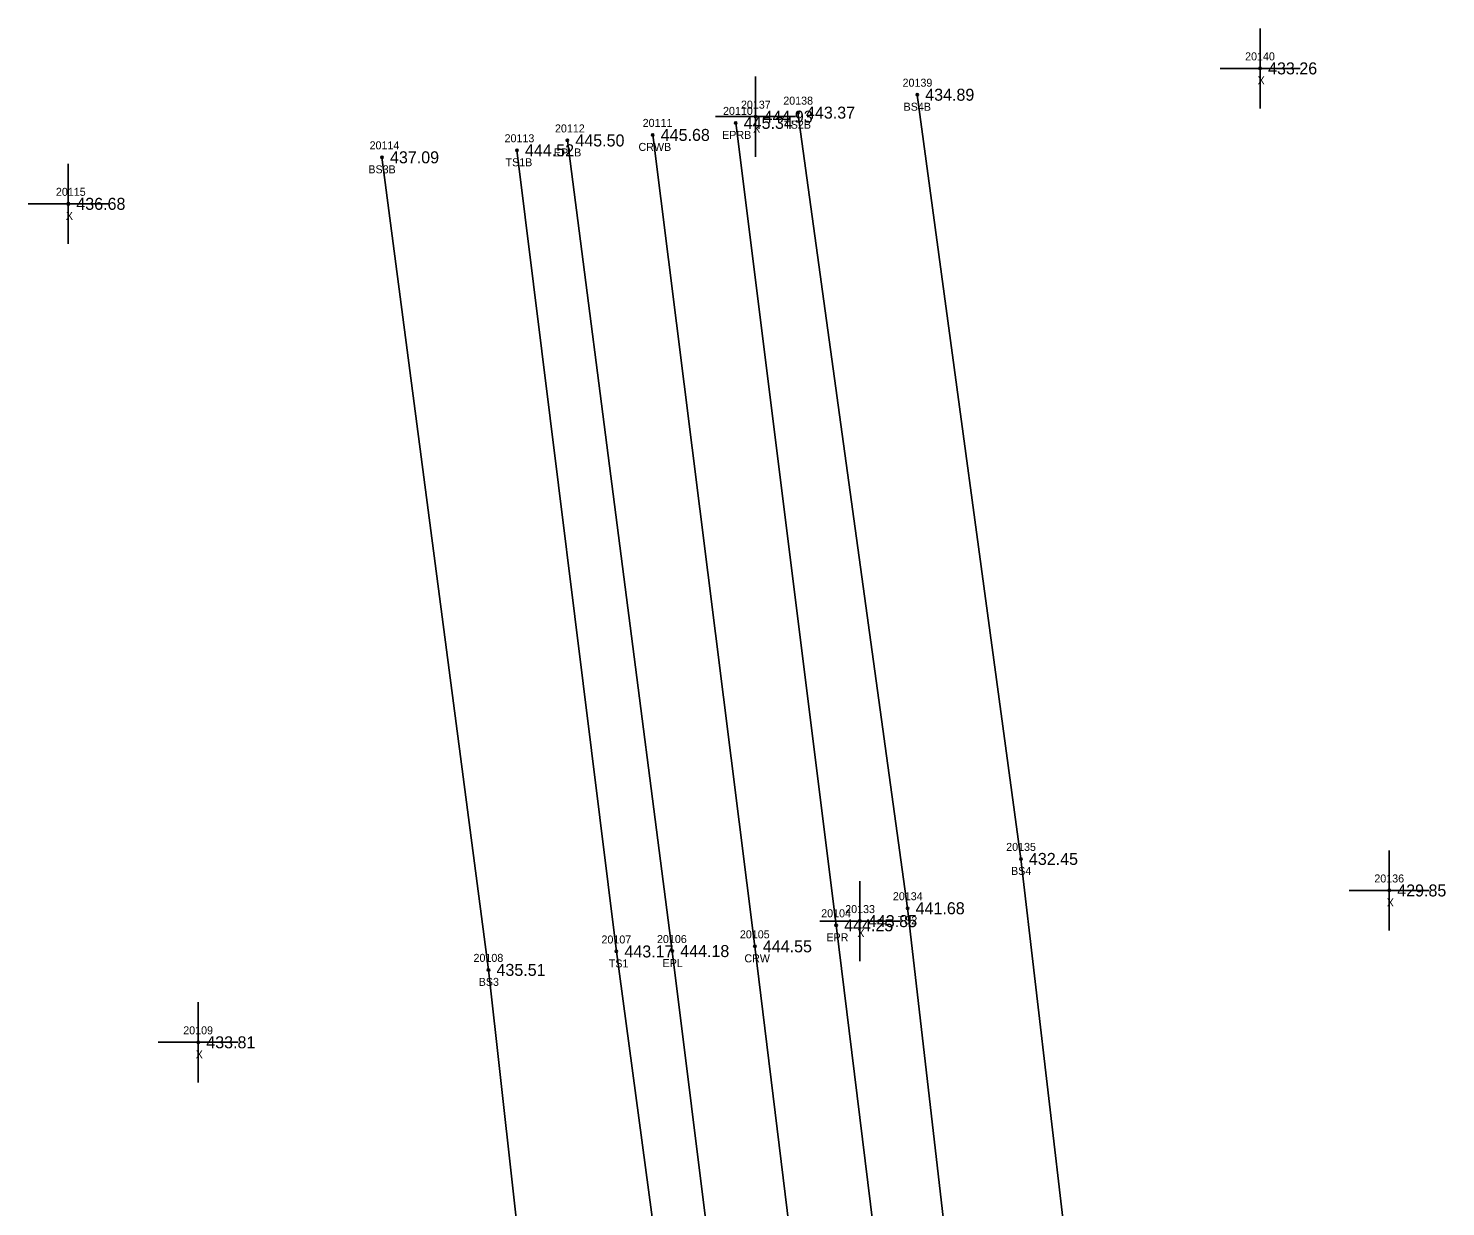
# Model space of a CAD drawing. Extents: x 1858461 to 1858936, y 1147060 to 1148183.
# Drawn here: x 1858539.2 to 1858716.4, y 1148023.6 to 1148170.7 of the extents above; entities that cross this region are included whole.
import ezdxf

# ---------------------------------------------------------------- set-up
doc = ezdxf.new("R2010")
doc.units = 0
for name, color, linetype in [('RD_DTM_BkLn1', 7, 'Continuous'), ('RD_DTM_BkLn2', 7, 'Continuous'), ('RD_DTM_BkLn_txCode', 7, 'Continuous'), ('RD_EX_Misc', 7, 'Continuous'), ('RD_EX_Misc_txCode', 7, 'Continuous'), ('RD_EX_Road', 7, 'Continuous'), ('RD_EX_Road_txCode', 7, 'Continuous'), ('RD_EX_TX_Misc_ELEV', 7, 'Continuous'), ('RD_EX_TX_Road_ELEV', 7, 'Continuous'), ('RD_HC_Survey_ELEV', 7, 'Continuous'), ('RD_HC_Survey_txCode', 7, 'Continuous'), ('RD_SMD_Locator', 7, 'Continuous')]:
    doc.layers.add(name, color=color, linetype=linetype)

msp = doc.modelspace()

# ---------------------------------------------------------------- linework, layer by layer
at = {"layer": 'RD_DTM_BkLn1'}
msp.add_lwpolyline([(1858679.02, 1147660.19), (1858666.85, 1147759.91), (1858654.47, 1147859.47), (1858641.87, 1147959.15), (1858630.02, 1148056.08), (1858617.26, 1148157.44)], dxfattribs=at)
at = {"layer": 'RD_DTM_BkLn2'}
for points in [[(1858693.62, 1147653.8), (1858703.51, 1147658.34), (1858709.65, 1147670.29), (1858700.15, 1147768.19), (1858693.67, 1147865.34), (1858675.79, 1147959.77), (1858663.27, 1148067), (1858650.31, 1148162.46)], [(1858691.24, 1147663), (1858693.74, 1147672.32), (1858681.4, 1147761.99), (1858668.07, 1147861.46), (1858660.68, 1147960.55), (1858649.11, 1148060.84), (1858635.41, 1148160.22)], [(1858693.62, 1147653.8), (1858663.6, 1147639.15), (1858647.78, 1147639.17), (1858628.12, 1147754.45), (1858616.79, 1147851.29), (1858607.32, 1147958.26), (1858596.73, 1148053.14), (1858583.42, 1148154.64)], [(1858665.51, 1147658.67), (1858661.09, 1147664.96), (1858652.2, 1147758.21), (1858640.05, 1147857.23), (1858625.95, 1147957.13), (1858612.72, 1148055.44), (1858600.29, 1148155.52)]]:
    msp.add_lwpolyline(points, dxfattribs=at)
at = {"layer": 'RD_EX_Misc'}
for p, q in [((1858693.16, 1148160.75), (1858693.16, 1148170.75)), ((1858630.11, 1148154.72), (1858630.11, 1148164.72)), ((1858688.16, 1148165.75), (1858698.16, 1148165.75)), ((1858625.11, 1148159.72), (1858635.11, 1148159.72)), ((1858544.22, 1148143.83), (1858544.22, 1148153.83)), ((1858539.22, 1148148.83), (1858549.22, 1148148.83)), ((1858709.3, 1148058.06), (1858709.3, 1148068.06)), ((1858643.15, 1148054.23), (1858643.15, 1148064.23)), ((1858704.3, 1148063.06), (1858714.3, 1148063.06)), ((1858638.15, 1148059.23), (1858648.15, 1148059.23)), ((1858560.46, 1148039.09), (1858560.46, 1148049.09)), ((1858555.46, 1148044.09), (1858565.46, 1148044.09))]:
    msp.add_line(p, q, dxfattribs=at)
at = {"layer": 'RD_EX_Road'}
for points in [[(1858679.02, 1147660.19), (1858688.73, 1147661.54), (1858677.21, 1147761.6), (1858664.75, 1147860.38), (1858652.33, 1147959.9), (1858640.18, 1148058.71), (1858627.63, 1148158.94)], [(1858679.02, 1147660.19), (1858669.49, 1147658.82), (1858657, 1147758.92), (1858643.96, 1147857.84), (1858631.87, 1147958), (1858619.69, 1148055.49), (1858606.59, 1148156.75)]]:
    msp.add_lwpolyline(points, dxfattribs=at)
at = {"layer": 'RD_SMD_Locator'}
for centre in [(1858693.16, 1148165.75), (1858650.31, 1148162.46), (1858630.11, 1148159.72), (1858635.41, 1148160.22), (1858617.26, 1148157.44), (1858627.63, 1148158.94), (1858600.29, 1148155.52), (1858606.59, 1148156.75), (1858583.42, 1148154.64), (1858544.22, 1148148.83), (1858663.27, 1148067), (1858709.3, 1148063.06), (1858649.11, 1148060.84), (1858640.18, 1148058.71), (1858643.15, 1148059.23), (1858612.72, 1148055.44), (1858619.69, 1148055.49), (1858630.02, 1148056.08), (1858596.73, 1148053.14), (1858560.46, 1148044.09)]:
    msp.add_circle(centre, 0.15, dxfattribs=at)

# ---------------------------------------------------------------- texts
at = {"layer": 'RD_DTM_BkLn_txCode'}
for s, p in [('20139', (1858648.48, 1148163.46)), ('20138', (1858633.57, 1148161.22)), ('BS4B', (1858648.61, 1148160.46)), ('TS2B', (1858633.69, 1148158.22)), ('20113', (1858598.74, 1148156.52)), ('20114', (1858581.87, 1148155.64)), ('TS1B', (1858598.86, 1148153.52)), ('BS3B', (1858581.72, 1148152.64)), ('20135', (1858661.43, 1148068)), ('BS4', (1858662.04, 1148065)), ('20134', (1858647.27, 1148061.84)), ('TS2', (1858647.86, 1148058.84)), ('20107', (1858610.85, 1148056.44)), ('20108', (1858594.86, 1148054.14)), ('TS1', (1858611.76, 1148053.44)), ('BS3', (1858595.51, 1148051.14))]:
    msp.add_text(s, height=1, dxfattribs=at).set_placement(p)
at = {"layer": 'RD_EX_Misc_txCode'}
for s, p in [('20140', (1858691.29, 1148166.75)), ('X', (1858692.85, 1148163.75)), ('20137', (1858628.28, 1148160.72)), ('X', (1858629.8, 1148157.72)), ('20115', (1858542.67, 1148149.83)), ('X', (1858543.91, 1148146.83)), ('20136', (1858707.44, 1148064.06)), ('X', (1858708.99, 1148061.06)), ('20133', (1858641.31, 1148060.23)), ('X', (1858642.83, 1148057.23)), ('20109', (1858558.58, 1148045.09)), ('X', (1858560.14, 1148042.09))]:
    msp.add_text(s, height=1, dxfattribs=at).set_placement(p)
at = {"layer": 'RD_EX_Road_txCode'}
for s, p in [('20110', (1858626.04, 1148159.94)), ('20112', (1858605.04, 1148157.75)), ('EPRB', (1858625.93, 1148156.94)), ('EPLB', (1858604.91, 1148154.75)), ('20104', (1858638.31, 1148059.71)), ('20106', (1858617.79, 1148056.49)), ('EPR', (1858638.96, 1148056.71)), ('EPL', (1858618.49, 1148053.49))]:
    msp.add_text(s, height=1, dxfattribs=at).set_placement(p)
at = {"layer": 'RD_EX_TX_Misc_ELEV'}
for s, p in [('433.26', (1858694.16, 1148165)), ('434.89', (1858651.31, 1148161.71)), ('443.37', (1858636.41, 1148159.47)), ('444.93', (1858631.11, 1148158.97)), ('444.52', (1858601.29, 1148154.77)), ('437.09', (1858584.42, 1148153.89)), ('436.68', (1858545.22, 1148148.08)), ('432.45', (1858664.27, 1148066.25)), ('429.85', (1858710.3, 1148062.31)), ('443.85', (1858644.15, 1148058.48)), ('441.68', (1858650.11, 1148060.09)), ('443.17', (1858613.72, 1148054.69)), ('435.51', (1858597.73, 1148052.39)), ('433.81', (1858561.46, 1148043.34))]:
    msp.add_text(s, height=1.5, dxfattribs=at).set_placement(p)
at = {"layer": 'RD_EX_TX_Road_ELEV'}
for s, p in [('445.34', (1858628.63, 1148158.19)), ('445.50', (1858607.59, 1148156)), ('444.25', (1858641.18, 1148057.96)), ('444.18', (1858620.69, 1148054.74))]:
    msp.add_text(s, height=1.5, dxfattribs=at).set_placement(p)
at = {"layer": 'RD_HC_Survey_ELEV'}
for s, p in [('445.68', (1858618.26, 1148156.69)), ('444.55', (1858631.02, 1148055.33))]:
    msp.add_text(s, height=1.5, dxfattribs=at).set_placement(p)
at = {"layer": 'RD_HC_Survey_txCode'}
for s, p in [('20111', (1858616, 1148158.44)), ('CRWB', (1858615.48, 1148155.44)), ('20105', (1858628.15, 1148057.08)), ('CRW', (1858628.71, 1148054.08))]:
    msp.add_text(s, height=1, dxfattribs=at).set_placement(p)

doc.saveas('drawing.dxf')
